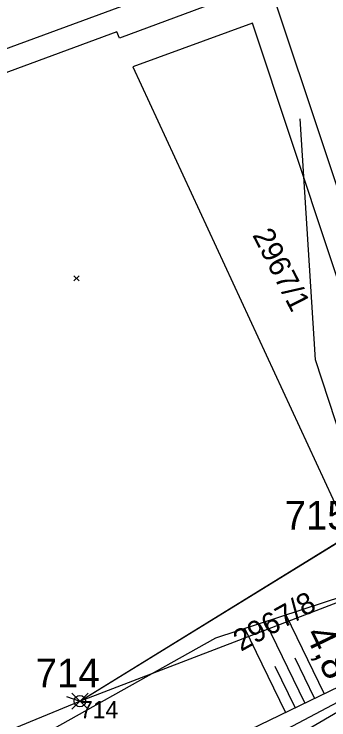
# Model space of a CAD drawing. Extents: x -800194 to -799078, y -1007177 to -1006597.
# Drawn here: x -799524.27 to -799502.31, y -1006953.32 to -1006904.06 of the extents above; entities that cross this region are included whole.
import ezdxf

# ---------------------------------------------------------------- set-up
doc = ezdxf.new("R2010")
doc.units = 0
for name, color, linetype in [('02_Osa_koleje', 7, 'Continuous'), ('Obvod stavby', 7, 'Continuous'), ('Vrstva 4', 7, 'Continuous'), ('Vrstva 48', 7, 'Continuous'), ('Vrstva 49', 7, 'Continuous'), ('Vrstva 51', 7, 'Continuous'), ('Vrstva 53', 7, 'Continuous'), ('Vrstva 55', 7, 'Continuous'), ('Vrstva 56', 7, 'Continuous'), ('Vrstva 57', 7, 'Continuous'), ('Vrstva 6', 7, 'Continuous'), ('Vrstva 60', 7, 'Continuous')]:
    doc.layers.add(name, color=color, linetype=linetype)

msp = doc.modelspace()

# ---------------------------------------------------------------- linework, layer by layer
at = {"layer": '02_Osa_koleje'}
msp.add_arc((-799651.022, -1006703.891), 292, 255.62486, 308.20516, dxfattribs=at)
at = {"layer": 'Obvod stavby'}
for p, q in [((-799520.246, -1006952.576), (-799519.114, -1006951.444)), ((-799520.246, -1006951.444), (-799519.114, -1006952.576))]:
    msp.add_line(p, q, dxfattribs=at)
msp.add_lwpolyline([(-799559.64, -1006968.48), (-799519.68, -1006952.01), (-799500.87, -1006940.41), (-799496.64, -1006937.8), (-799494.85, -1006936.7), (-799484.52, -1006930.32), (-799457.99, -1006908.8), (-799435, -1006885.17), (-799430.26, -1006880.27), (-799425.53, -1006875.38), (-799422.55, -1006864.36), (-799416.748, -1006858.798), (-799395.763, -1006879.374), (-799413.75, -1006898.23), (-799418.41, -1006902.53), (-799423.07, -1006906.83), (-799433.4, -1006916.39), (-799469.5, -1006946.86), (-799487.22, -1006958.47), (-799495.25, -1006963.74), (-799521.98, -1006977.8), (-799546.71, -1006987.83)], dxfattribs=at)
msp.add_circle((-799519.68, -1006952.01), 0.4, dxfattribs=at)
at = {"layer": 'Vrstva 4'}
for points in [[(-799511.236, -1006957.129), (-799499.236, -1006950.771), (-799498.598, -1006949.914), (-799498.679, -1006949.705), (-799496.151, -1006948.479), (-799496.251, -1006948.258), (-799490.687, -1006944.683), (-799490.497, -1006944.878), (-799488.249, -1006943.052), (-799488.105, -1006943.216), (-799486.269, -1006941.68), (-799478.997, -1006936.484), (-799474.568, -1006932.916), (-799474.237, -1006932.694), (-799461.519, -1006921.99), (-799452.935, -1006914.372), (-799444.695, -1006906.886), (-799436.579, -1006898.932), (-799429.629, -1006892.192), (-799429.07, -1006892.727), (-799423.479, -1006886.901), (-799416.56, -1006880.007), (-799417.085, -1006879.46), (-799415.349, -1006878.386)], [(-799510.726, -1006958.045), (-799497.901, -1006950.516), (-799478.36, -1006937.055), (-799461.534, -1006923.53), (-799452.128, -1006915.305), (-799443.894, -1006907.632), (-799435.739, -1006899.754), (-799428.922, -1006893.007), (-799423.223, -1006887.256), (-799416.277, -1006880.269), (-799414.896, -1006878.87)]]:
    msp.add_lwpolyline(points, dxfattribs=at)
at = {"layer": 'Vrstva 48'}
for p, q in [((-799502.636, -1006951.48), (-799505.288, -1006946.002)), ((-799503.986, -1006952.133), (-799506.726, -1006946.474)), ((-799505.336, -1006952.787), (-799508.163, -1006946.947)), ((-799503.311, -1006951.806), (-799504.659, -1006949.022)), ((-799504.661, -1006952.46), (-799506.053, -1006949.585))]:
    msp.add_line(p, q, dxfattribs=at)
at = {"layer": 'Vrstva 49'}
for p, q in [((-799520.095, -1006922.327), (-799519.741, -1006922.681)), ((-799520.095, -1006922.681), (-799519.741, -1006922.327)), ((-799520.095, -1006922.327), (-799519.741, -1006922.681)), ((-799520.095, -1006922.681), (-799519.741, -1006922.327))]:
    msp.add_line(p, q, dxfattribs=at)
for points in [[(-799496.989, -1006948.551), (-799501.292, -1006944.69), (-799510.22, -1006947.622)], [(-799510.22, -1006947.622), (-799525.177, -1006955.998), (-799527.677, -1006951.163), (-799532.773, -1006952.141), (-799538.673, -1006961.225), (-799541.203, -1006964.827)], [(-799512.053, -1006955.956), (-799509.8, -1006954.937), (-799509.204, -1006954.659), (-799500.879, -1006950.629), (-799498.679, -1006949.705), (-799499.015, -1006949.821), (-799499.13, -1006949.555), (-799496.989, -1006948.551)]]:
    msp.add_lwpolyline(points, dxfattribs=at)
at = {"layer": 'Vrstva 51'}
msp.add_lwpolyline([(-799487.284, -1006968.607), (-799490.087, -1006954.678), (-799499.499, -1006939.61), (-799503.236, -1006928.194), (-799504.313, -1006911.364)], dxfattribs=at)
at = {"layer": 'Vrstva 53'}
msp.add_lwpolyline([(-799559.64, -1006968.48), (-799519.68, -1006952.01), (-799500.87, -1006940.41), (-799496.64, -1006937.8), (-799494.85, -1006936.7), (-799484.519, -1006930.319), (-799457.99, -1006908.8), (-799435, -1006885.17), (-799430.26, -1006880.27), (-799425.53, -1006875.38), (-799422.55, -1006864.36), (-799390.88, -1006834), (-799358.35, -1006806.65), (-799352.29, -1006801.56), (-799330.91, -1006783.58), (-799314.235, -1006766.649)], dxfattribs=at)
at = {"layer": 'Vrstva 55'}
msp.add_line((-799519.68, -1006952.01), (-799500.87, -1006940.41), dxfattribs=at)
for points in [[(-799586.79, -1006927.02), (-799561.07, -1006919.79), (-799500.17, -1006897.39), (-799498.58, -1006896.8)], [(-799506.49, -1006901.85), (-799516.91, -1006905.73), (-799517.11, -1006905.3), (-799557.12, -1006920.07)], [(-799494.85, -1006936.7), (-799505.77, -1006904), (-799506.49, -1006901.85)], [(-799496.64, -1006937.8), (-799507.65, -1006904.69), (-799515.98, -1006907.74), (-799500.87, -1006940.41)], [(-799519.68, -1006952.01), (-799500.6, -1006944.68), (-799499.96, -1006942.39), (-799500.87, -1006940.41)], [(-799667.43, -1006981.06), (-799637.16, -1006982.06), (-799603.07, -1006978.39), (-799559.64, -1006968.48), (-799519.68, -1006952.01)]]:
    msp.add_lwpolyline(points, dxfattribs=at)
at = {"layer": 'Vrstva 56'}
msp.add_line((-799520.626, -1006951.684), (-799519.68, -1006952.009), dxfattribs=at)
at = {"layer": 'Vrstva 60'}
msp.add_line((-799519.68, -1006952.01), (-799519.68, -1006952.01), dxfattribs=at)

# ---------------------------------------------------------------- texts
at = {"layer": 'Obvod stavby'}
for s, p in [('715', (-799505.397, -1006940.033)), ('714', (-799522.762, -1006951.046))]:
    msp.add_text(s, height=2, rotation=360, dxfattribs=at).set_placement(p)
at = {"layer": 'Vrstva 48'}
msp.add_text('4,8', height=2, rotation=295.8309, dxfattribs=at).set_placement((-799504.015, -1006947.319))
at = {"layer": 'Vrstva 57'}
for s, rotation, p in [('2967/1', 297, (-799507.67, -1006919.476)), ('2967/8', 29, (-799508.447, -1006948.573))]:
    msp.add_text(s, height=1.5, rotation=rotation, dxfattribs=at).set_placement(p)
at = {"layer": 'Vrstva 6'}
msp.add_text('km 204,491', height=2.5, rotation=308.1328, dxfattribs=at).set_placement((-799504.737, -1006892.946))
at = {"layer": 'Vrstva 60'}
msp.add_text('714', height=1.2, dxfattribs=at).set_placement((-799519.68, -1006953.21))

doc.saveas('drawing.dxf')
